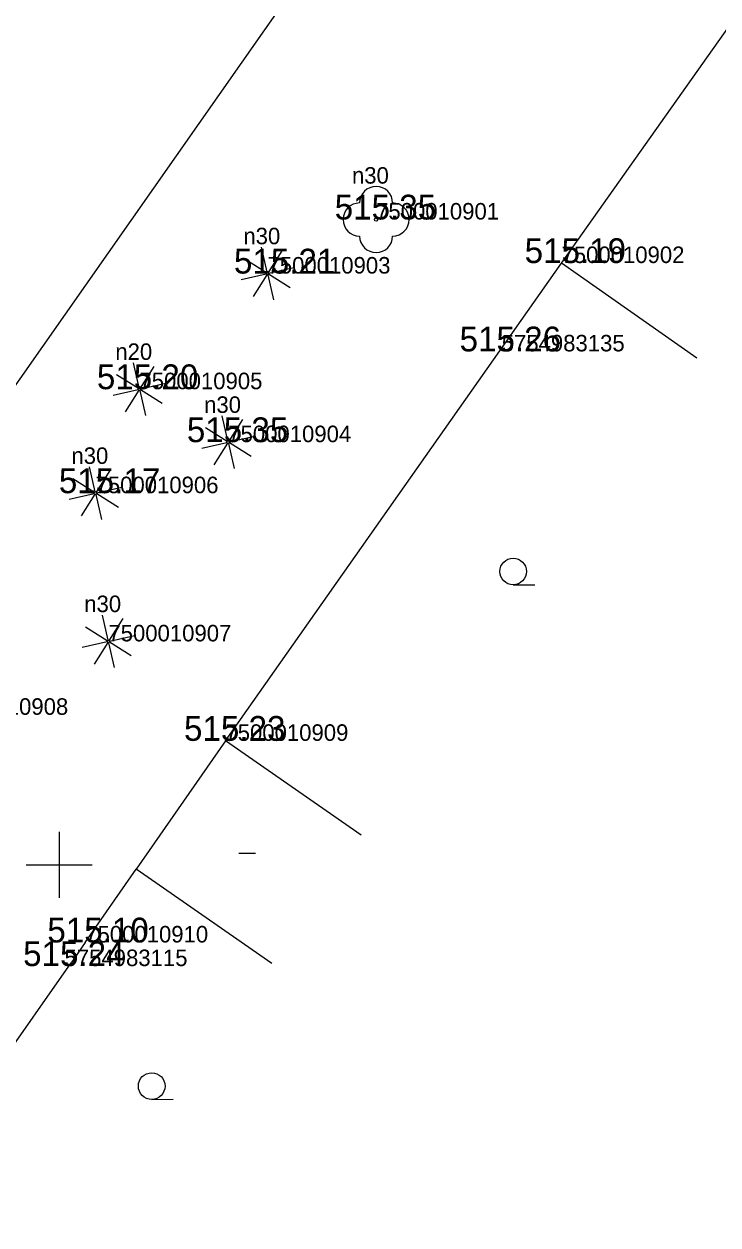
# Model space of a CAD drawing. Extents: x -669251 to -668549, y -1128351 to -1127698.
# Drawn here: x -668951.06 to -668930.08, y -1128010.9 to -1127974.55 of the extents above; entities that cross this region are included whole.
import ezdxf

# ---------------------------------------------------------------- set-up
doc = ezdxf.new("R2010")
doc.units = 0
for name, color, linetype in [('Vrstva 1', 7, 'Continuous'), ('Vrstva 10', 7, 'Continuous'), ('Vrstva 2', 7, 'Continuous'), ('Vrstva 22', 7, 'Continuous'), ('Vrstva 3', 7, 'Continuous'), ('Vrstva 36', 7, 'Continuous'), ('Vrstva 47', 7, 'Continuous'), ('Vrstva 5', 7, 'Continuous'), ('Vrstva 58', 7, 'Continuous'), ('Vrstva 61', 7, 'Continuous'), ('Vrstva 7', 7, 'Continuous'), ('Vrstva 8', 7, 'Continuous')]:
    doc.layers.add(name, color=color, linetype=linetype)

msp = doc.modelspace()

# ---------------------------------------------------------------- linework, layer by layer
at = {"layer": 'Vrstva 1'}
for p, q in [((-668940.416, -1127980.471), (-668940.416, -1127980.471)), ((-668934.81, -1127981.788), (-668934.81, -1127981.788)), ((-668943.7, -1127982.106), (-668943.7, -1127982.106)), ((-668936.618, -1127984.462), (-668936.618, -1127984.462)), ((-668947.572, -1127985.606), (-668947.572, -1127985.606)), ((-668944.887, -1127987.209), (-668944.887, -1127987.209)), ((-668948.9, -1127988.753), (-668948.9, -1127988.753)), ((-668948.512, -1127993.238), (-668948.512, -1127993.238)), ((-668944.973, -1127996.248), (-668944.973, -1127996.248)), ((-668949.212, -1128002.35), (-668949.212, -1128002.35)), ((-668949.838, -1128003.065), (-668949.838, -1128003.065))]:
    msp.add_line(p, q, dxfattribs=at)
at = {"layer": 'Vrstva 10'}
msp.add_line((-668962.731, -1128001.775), (-668942.246, -1127972.533), dxfattribs=at)
at = {"layer": 'Vrstva 22'}
for p, q in [((-668943.708, -1127982.066), (-668943.88, -1127981.312)), ((-668943.734, -1127982.086), (-668944.39, -1127981.672)), ((-668943.266, -1127981.416), (-668943.68, -1127982.072)), ((-668943.66, -1127982.098), (-668942.906, -1127981.926)), ((-668944.494, -1127982.286), (-668943.74, -1127982.114)), ((-668943.72, -1127982.14), (-668944.134, -1127982.796)), ((-668943.692, -1127982.146), (-668943.52, -1127982.9)), ((-668943.01, -1127982.54), (-668943.666, -1127982.126)), ((-668947.58, -1127985.566), (-668947.752, -1127984.812)), ((-668947.138, -1127984.916), (-668947.552, -1127985.572)), ((-668947.606, -1127985.586), (-668948.262, -1127985.172)), ((-668948.366, -1127985.786), (-668947.612, -1127985.614)), ((-668947.592, -1127985.64), (-668948.006, -1127986.296)), ((-668947.564, -1127985.646), (-668947.392, -1127986.4)), ((-668946.882, -1127986.04), (-668947.538, -1127985.626)), ((-668947.532, -1127985.598), (-668946.778, -1127985.426)), ((-668944.895, -1127987.169), (-668945.067, -1127986.415)), ((-668944.921, -1127987.189), (-668945.577, -1127986.775)), ((-668944.453, -1127986.519), (-668944.867, -1127987.175)), ((-668944.847, -1127987.201), (-668944.093, -1127987.029)), ((-668945.681, -1127987.389), (-668944.927, -1127987.217)), ((-668944.907, -1127987.243), (-668945.321, -1127987.899)), ((-668944.879, -1127987.249), (-668944.707, -1127988.003)), ((-668944.197, -1127987.643), (-668944.853, -1127987.229)), ((-668948.908, -1127988.713), (-668949.08, -1127987.959)), ((-668948.466, -1127988.063), (-668948.88, -1127988.719)), ((-668948.934, -1127988.733), (-668949.59, -1127988.319)), ((-668948.86, -1127988.745), (-668948.106, -1127988.573)), ((-668949.694, -1127988.933), (-668948.94, -1127988.761)), ((-668948.92, -1127988.787), (-668949.334, -1127989.443)), ((-668948.892, -1127988.793), (-668948.72, -1127989.547)), ((-668948.21, -1127989.187), (-668948.866, -1127988.773)), ((-668948.52, -1127993.198), (-668948.692, -1127992.444)), ((-668948.078, -1127992.548), (-668948.492, -1127993.204)), ((-668948.546, -1127993.218), (-668949.202, -1127992.804)), ((-668949.306, -1127993.418), (-668948.552, -1127993.246)), ((-668948.532, -1127993.272), (-668948.946, -1127993.928)), ((-668948.504, -1127993.278), (-668948.332, -1127994.032)), ((-668947.822, -1127993.672), (-668948.478, -1127993.258)), ((-668948.472, -1127993.23), (-668947.718, -1127993.058))]:
    msp.add_line(p, q, dxfattribs=at)
for centre, radius in [((-668940.416, -1127980.471), 0.05), ((-668943.7, -1127982.106), 0.04), ((-668947.572, -1127985.606), 0.04), ((-668944.887, -1127987.209), 0.04), ((-668948.9, -1127988.753), 0.04), ((-668948.512, -1127993.238), 0.04)]:
    msp.add_circle(centre, radius, dxfattribs=at)
for centre, start, end in [((-668940.416, -1127979.971), 0, 180), ((-668940.916, -1127980.471), 90, 270), ((-668939.916, -1127980.471), 270, 90), ((-668940.416, -1127980.971), 180, 0)]:
    msp.add_arc(centre, 0.5, start, end, dxfattribs=at)
at = {"layer": 'Vrstva 36'}
for p, q in [((-668936.271, -1127991.525), (-668935.621, -1127991.522)), ((-668947.202, -1128007.099), (-668946.552, -1128007.096))]:
    msp.add_line(p, q, dxfattribs=at)
for centre in [(-668936.271, -1127991.122), (-668947.202, -1128006.696)]:
    msp.add_circle(centre, 0.403, dxfattribs=at)
at = {"layer": 'Vrstva 5'}
for p, q in [((-668944.973, -1127996.248), (-668947.672, -1128000.133)), ((-668940.867, -1127999.101), (-668944.973, -1127996.248)), ((-668943.565, -1128002.985), (-668947.672, -1128000.133))]:
    msp.add_line(p, q, dxfattribs=at)
at = {"layer": 'Vrstva 58'}
msp.add_line((-668944.564, -1127999.65), (-668944.064, -1127999.65), dxfattribs=at)
at = {"layer": 'Vrstva 61'}
for p, q in [((-668950, -1127999), (-668950, -1128001)), ((-668951, -1128000), (-668949, -1128000))]:
    msp.add_line(p, q, dxfattribs=at)
at = {"layer": 'Vrstva 7'}
for p, q in [((-668934.81, -1127981.788), (-668924.409, -1127967.078)), ((-668944.973, -1127996.248), (-668934.81, -1127981.788)), ((-668930.719, -1127984.663), (-668934.81, -1127981.788)), ((-668949.212, -1128002.35), (-668947.672, -1128000.133)), ((-668955.179, -1128010.9), (-668949.641, -1128002.965))]:
    msp.add_line(p, q, dxfattribs=at)
at = {"layer": 'Vrstva 8'}
msp.add_line((-668949.212, -1128002.35), (-668949.641, -1128002.965), dxfattribs=at)

# ---------------------------------------------------------------- texts
at = {"layer": 'Vrstva 2'}
for s, p in [('7500010901', (-668940.416, -1127980.471)), ('7500010902', (-668934.81, -1127981.788)), ('7500010903', (-668943.7, -1127982.106)), ('5754983135', (-668936.618, -1127984.462)), ('7500010905', (-668947.572, -1127985.606)), ('7500010904', (-668944.887, -1127987.209)), ('7500010906', (-668948.9, -1127988.753)), ('7500010907', (-668948.512, -1127993.238)), ('7500010908', (-668953.444, -1127995.46)), ('7500010909', (-668944.973, -1127996.248)), ('7500010910', (-668949.212, -1128002.35)), ('5754983115', (-668949.838, -1128003.065))]:
    msp.add_text(s, height=0.5, dxfattribs=at).set_placement(p)
at = {"layer": 'Vrstva 3'}
for s, p in [('515.35 ', (-668941.668, -1127980.471)), ('515.21 ', (-668944.715, -1127982.106)), ('515.19 ', (-668935.924, -1127981.788)), ('515.26 ', (-668937.892, -1127984.462)), ('515.20 ', (-668948.86, -1127985.606)), ('515.35 ', (-668946.139, -1127987.209)), ('515.17 ', (-668950.01, -1127988.753)), ('515.23 ', (-668946.225, -1127996.248)), ('515.10 ', (-668950.358, -1128002.35)), ('515.24 ', (-668951.09, -1128003.065))]:
    msp.add_text(s, height=0.75, dxfattribs=at).set_placement(p)
at = {"layer": 'Vrstva 47'}
for s, height, p in [('n30', 0.499, (-668941.145, -1127979.385)), ('n30', 0.5, (-668944.43, -1127981.22)), ('n20', 0.5, (-668948.302, -1127984.72)), ('n30', 0.5, (-668945.617, -1127986.323)), ('n30', 0.5, (-668949.63, -1127987.867)), ('n30', 0.5, (-668949.242, -1127992.352))]:
    msp.add_text(s, height=height, dxfattribs=at).set_placement(p)

doc.saveas('drawing.dxf')
